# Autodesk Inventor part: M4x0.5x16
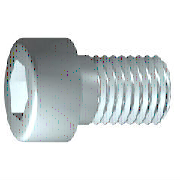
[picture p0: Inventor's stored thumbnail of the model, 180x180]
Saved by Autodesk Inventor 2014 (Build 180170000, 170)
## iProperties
IsCustomPart: 1
Company: 한국ATC센터
Created: 2009-02
Part Number: M4x0.5x16
Material: 강, 연강
Description: 6각머리 태핑 나사
Document SubType Name: Modeling
Standard: KS B 1003
Designer: KYOUNG IL JANG
Standards Organization: KS
Language: ko-KR
Size Designation: M 4 x 16
Categories: <MemberInstance><Categories><Category DisplayName="조임쇠" InternalName="e4da775c-781d-43d5-af7c-5136215cf5a6" Mnemonic="FSTN"><Category DisplayName="볼트" InternalN
Density: 7.86 g/cm^3
Mass: 2.62973 g
Surface Area: 3.81119 cm^2
Volume: 0.334572 cm^3
Vendor: CBT Solutions
Appearance: 연마 - 진회색
Author: KYOUNG IL JANG
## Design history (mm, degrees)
sketch "스케치1"
  geometry: L1 (-1, 0)-(16, 0); L2 (16, 0)-(16, 2); L3 (16, 2)-(1.75, 2); L4 (1.75, 2)-(1.32, 2); L5 (1.32, 2)-(0, 2); L6 (0, 2)-(0, 3.5); L7 (0, 3.5)-(-4, 3.5); L8 (-4, 3.5)-(-4, 1.732); L9 (-4, 1.732)-(-2, 1.732); L10 (-2, 1.732)-(-1, 0); L11 (-8, 0)-(20, 0) reference; L12 (0, -0.7)-(0, 4.2) reference; L13 (1.75, 2)-(0, 2)
  constraints: 22 end point, 6 parallel, 2 collinear, 2 perpendicular, 1 horizontal, 1 point on line
  dimensions: "d1" = 14.25 distance from line of L3.end L2 (= GEL); "d2" = 0.42952 distance of L4.end L3.end (computed from GAL); "d3" = 4 distance between parallel lines of L8 L6 (= KOH); "d4" = 2 distance of L8.end L9.end (= INTI); "d5" = 60 deg angle of L10 L1; "d6" = 4 diameter of L3 L1 (= GD); "d7" = 4 diameter of L5 L1 (= BDM); "d8" = 3.4641 diameter of L9 L1 (= 1.1547 x SW); "d9" = 7 diameter of L7 L1 (= KOD); "d26" = 16 distance between parallel lines of L12 L2 (= NLG)
revolve "본체" sketch "스케치1" stored, may be unused: angle "d10" = 90 deg
sketch "스케치2"
  geometry: L1 (0, -4.9)-(0, 4.9) reference; L2 (-4.9, 0)-(4.9, 0) reference; L3 (1.732, 0)-(0.866, -1.5); L4 (0.866, -1.5)-(-0.866, -1.5); L5 (-0.866, -1.5)-(-1.732, 0); L6 (-1.732, 0)-(-0.866, 1.5); L7 (-0.866, 1.5)-(0.866, 1.5); L8 (0.866, 1.5)-(1.732, 0); 2 further points
  constraints: 12 end point, 1 coincident, 1 horizontal alignment, 1 point on line, 12 other
extrude "슬롯" join sketch "스케치2" stored distance "d11" = 10; taper "d12" = 0 deg
workplane "Work Plane1"
fillet "Fillet2" dims "d30" = 0.1 (= R)
body "Solid1"
fillet "모깎기1" dims "d17" = 0.4 (= RR)
feature "스레드" dims "d13" = 14.25 (= GEL), "d14" = 0
chamfer "모따기1" distance "d15" = 0.42941 (= -0.5 x SPD + 0.5 x GD); stored, may be unused: second distance "d16" = 0.42941 (= GUL), angle "d27" = 45 deg
other parameters: "GD" = 4 (= NND) [user parameter; used in 2 equation terms], "NLG" = 16 [user parameter; used in 1 equation term], "GEL" = 14.25 [user parameter; used in 2 equation terms], "KOD" = 7 [user parameter; used in 1 equation term], "KOH" = 4 [user parameter; used in 1 equation term], "INTI" = 2 [user parameter; used in 1 equation term], "GAL" = 0.42941 (= 0.61345 x PTC) [user parameter; used in 1 equation term], "GUL" = 0.42941 (= 0.61345 x PTC) [user parameter; used in 1 equation term], "BDM" = 4 (= NND) [user parameter; used in 1 equation term], "SW" = 3 [user parameter; used in 2 equation terms], "RR" = 0.4 [user parameter; used in 1 equation term], "SPD" = 3.14117 (= NND - 1.2269 x PTC) [user parameter; used in 1 equation term], "d19" = 0, "d28" = 0, "d29" = 0, "R" = 0.1 [user parameter; used in 1 equation term], "PHH" = 0.2 [user parameter], "GD1" = 3.14117 (= THREADDIA - 1.2269 x PTC) [user parameter], "THREADDIA" = 4 [user parameter; used in 1 equation term], "FAWI" = 45 deg [user parameter], "TPU" = 14.28571 (computed from PTC) [user parameter], "PTC" = 0.7 [user parameter; used in 5 equation terms], "NND" = 4 [user parameter; used in 3 equation terms], "TOA" = 30 deg [user parameter], "E0" = 3.465 (= 1.155 x SW) [user parameter]
